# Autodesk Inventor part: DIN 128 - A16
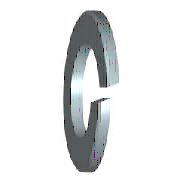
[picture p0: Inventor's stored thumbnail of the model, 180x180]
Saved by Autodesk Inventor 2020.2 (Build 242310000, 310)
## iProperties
Created: 2019-01
Part Number: DIN 128 - A16
Material: Stahl, weich
Description: Federring
Document SubType Name: Modeling
Standard: DIN 128
Designer: lutzd
Standard Revision: 1994
Standards Organization: DIN
Language: de-DE
Size Designation: A16
Categories: <MemberInstance><Categories><Category DisplayName="Verbindungselemente" InternalName="e4da775c-781d-43d5-af7c-5136215cf5a6" Mnemonic="FSTN"><Category DisplayNam
Density: 7.85 g/cm^3
Appearance: Halbpoliert
IsCustomPart: 0
Author: lutzd
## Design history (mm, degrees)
sketch "Skizze1"
  geometry: C1 r 13.7 at (0, 0); C2 r 8.5 at (0, 0); 1 further point
  constraints: 2 centre point, 2 coincident
  dimensions: "d0" = 17 diameter of C2 (= SD1); "d1" = 27.4 diameter of C1 (= SD2)
extrude "Körper" new body sketch "Skizze1" distance "d2" = 2.8 (= SD); taper "d3" = 0 deg
sketch "Skizze2"
  geometry: L1 (0, -8.5)-(0, 8.5) reference; L2 (2.8, 13.7)-(2.8, -13.7) reference; L3 (-1.2, 0)-(7.2, 0) reference; L4 (0, -0.56)-(2.8, 1.057); L5 (0, 0.56)-(2.8, 2.177)
  constraints: 4 end point, 4 point on line, 1 parallel
  dimensions: "d4" = 0.56 distance from line of L3 L4.start (= 0.2 x SD); "d5" = 0.56 distance from line of L3 L5.start (= 0.2 x SD); "d6" = 60 deg angle of L2 L4 (= FAWI)
extrude "Schnitt" cut sketch "Skizze2" stored distance "d7" = 2.8 (= SD); taper "d8" = 0 deg
workaxis "Work Axis1"
workplane "Work Plane1"
body "Solid1"
fillet "Rundung" dims "d13" = 1 (= R)
other parameters: "SD1" = 17 [user parameter; used in 1 equation term], "SD2" = 27.4 [user parameter; used in 1 equation term], "SD" = 2.8 [user parameter; used in 4 equation terms], "FAWI" = 60 deg [user parameter; used in 1 equation term], "d9" = 0, "d10" = 0, "d11" = 0, "d12" = 0, "R" = 1 [user parameter; used in 1 equation term], "NND" = 16 [user parameter]
